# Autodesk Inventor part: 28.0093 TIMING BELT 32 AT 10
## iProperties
Created: 2007-04
Part Number: 28.0093 TIMING BELT 32 AT 10
Document SubType Name: Modeling
Designer: Andy Moles
Material: UHMW, White
Density: 0.94 g/cm^3
Author: Andy Moles
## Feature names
1. Extrusion2
2. Rectangular Pattern1
